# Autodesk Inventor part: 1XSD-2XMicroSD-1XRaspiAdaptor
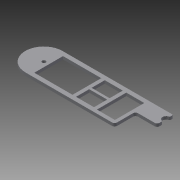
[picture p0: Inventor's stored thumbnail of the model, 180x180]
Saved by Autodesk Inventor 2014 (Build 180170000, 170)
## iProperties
Created: 2015-01
Part Number: 1XSD-2XMicroSD-1XRaspiAdaptor
Material: Generic
Document SubType Name: Modeling
Designer: Drano
Density: 1 g/cm^3
Appearance: Default
Author: Drano
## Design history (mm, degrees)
sketch "Sketch1"
  geometry: L1 (-32.767, -14.967)-(39.733, -14.967); L2 (-32.767, 16.033)-(58.733, 16.033); L3 (-28.767, -11.467)-(3.133, -11.467); L4 (3.133, -11.467)-(3.133, 12.533); L5 (-28.767, 12.533)-(3.133, 12.533); L6 (-28.767, -11.467)-(-28.767, 12.533); L7 (24.033, -11.967)-(39.033, -11.967); L8 (39.033, -11.967)-(39.033, 12.533); L9 (24.033, 12.533)-(39.033, 12.533); L10 (24.033, -11.967)-(24.033, 12.533); L11 (6.083, -11.467)-(21.083, -11.467); L12 (21.083, -11.467)-(21.083, -0.467); L13 (6.083, -0.467)-(21.083, -0.467); L14 (6.083, -11.467)-(6.083, -0.467); L15 (6.083, 1.533)-(21.083, 1.533); L16 (21.083, 1.533)-(21.083, 12.533); L17 (6.083, 12.533)-(21.083, 12.533); L18 (6.083, 1.533)-(6.083, 12.533); L19 (59.733, 4.533)-(59.733, 6.16); L20 (59.733, 13.906)-(59.733, 15.033); L21 (43.733, 2.533)-(57.733, 2.533); L22 (41.733, -12.967)-(41.733, 0.533); C1 r 1.5 at (-32.767, 0.533); A1 r 15.5 centre (-32.767, 0.533) between (-32.767, 16.033) and (-32.767, -14.967); A2 r 2 centre (39.733, -12.967) between (39.733, -14.967) and (41.733, -12.967); A3 r 1 centre (58.733, 15.033) between (59.733, 15.033) and (58.733, 16.033); A4 r 2 centre (57.733, 4.533) between (57.733, 2.533) and (59.733, 4.533); A5 r 3 centre (59.733, 10.033) between (58.983, 12.937) and (58.983, 7.128); A6 r 1 centre (58.733, 6.16) between (59.733, 6.16) and (58.983, 7.128); A7 r 1 centre (58.733, 13.906) between (58.983, 12.937) and (59.733, 13.906); A8 r 2 centre (43.733, 0.533) between (43.733, 2.533) and (41.733, 0.533); 1 further point
  constraints: 44 end point, 16 point on circle, 9 centre point
extrude "Extrusion1" new body sketch "Sketch1" distance "d0" = 2.5; taper "d1" = 0 deg
body "Solid1"
